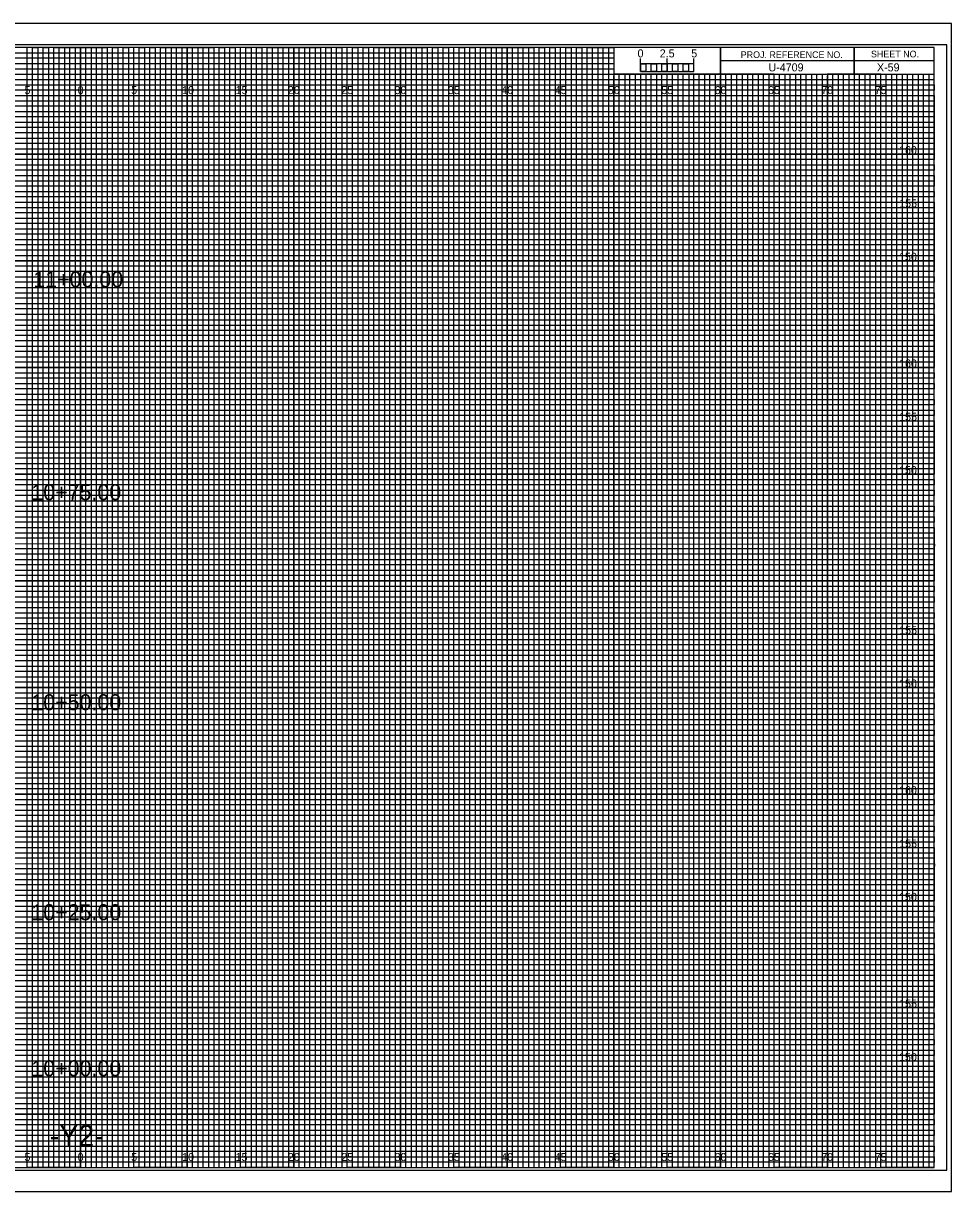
# Model space of a CAD drawing. Extents: x -7 to 162, y -2 to 107.
# Drawn here: x 74.6 to 161.7, y -2.3 to 107.3 of the extents above; entities that cross this region are included whole.
import ezdxf

# ---------------------------------------------------------------- set-up
doc = ezdxf.new("R2010")
doc.units = 0
for name, color, linetype in [('Exist CMT Pavement', 7, 'Continuous'), ('Prop CMT Pvmt Course 1 Wedge', 7, 'Continuous'), ('Prop CMT Pvmt Course 2 Wedge', 7, 'Continuous'), ('Prop CMT Pvmt Course 3 Wedge', 7, 'Continuous'), ('Prop CMT Pvmt Wedge Surface 1', 7, 'Continuous'), ('Prop CMT Pvmt Wedge Surface 2', 7, 'Continuous'), ('Prop CMT Pvmt Wedge Surface 3', 7, 'Continuous'), ('Prop CMT Shear Line', 7, 'Continuous'), ('Prop XS Alignment Label', 7, 'Continuous'), ('Prop XS Bar Scale Labels', 7, 'Continuous'), ('Prop XS Elevation Labels', 7, 'Continuous'), ('Prop XS Label Text', 7, 'Continuous'), ('Prop XS Project Number', 7, 'Continuous'), ('Prop XS Sheet Number', 7, 'Continuous'), ('Prop XS Station Labels', 7, 'Continuous'), ('Scratch_Level_1', 7, 'Continuous'), ('Sheet Cutting Line CELL', 7, 'Continuous')]:
    doc.layers.add(name, color=color, linetype=linetype)

msp = doc.modelspace()

# ---------------------------------------------------------------- linework, layer by layer
at = {"layer": 'Exist CMT Pavement'}
for p, q in [((0, 104.5), (130, 104.5)), ((130, 104.5), (130, 103.99)), ((130, 103.99), (0, 103.99)), ((0, 103.5), (130, 103.5)), ((130, 102.95), (0, 102.95)), ((130, 103.5), (130, 102.95)), ((0, 102), (160, 102))]:
    msp.add_line(p, q, dxfattribs=at)
for points in [[(0, 101.5), (135, 101.5), (160, 101.5), (160, 101), (0, 101)], [(0, 100.5), (160, 100.5), (160, 99.5), (0, 99.5)], [(0, 99), (160, 99), (160, 98.5), (0, 98.49)], [(0, 98), (160, 98), (160, 97), (0, 97)], [(0, 96.5), (160, 96.5), (160, 96), (0, 96)], [(0, 95.5), (160, 95.5), (160, 94.5), (0, 94.5)], [(0, 94), (160, 94), (160, 93.5), (0, 93.5)], [(0, 93), (160, 93), (160, 92), (0, 92)], [(0, 91.5), (160, 91.5), (160, 91), (0, 91)], [(0, 90.5), (160, 90.5), (160, 89.5), (0, 89.5)], [(0, 89), (160, 89), (160, 88.5), (0, 88.5)], [(0, 88), (160, 88), (160, 86.98), (160, 86.5), (160, 86), (0, 86)], [(0, 87), (160, 87), (160, 86.5), (0, 86.5)], [(0, 85.5), (160, 85.5), (160, 84.5), (0, 84.52)], [(0, 84.52), (160, 84.5), (160, 84), (0, 84)], [(0, 83.5), (160, 83.5), (160, 83), (0, 83)], [(0, 82), (160, 82), (160, 81.5), (0, 81.5)], [(0, 81), (160, 81), (160, 80.5), (0, 80.5)], [(-0.04, 79.45), (160, 79.45), (160, 78.94), (-0.04, 78.94)], [(0, 78.5), (160, 78.5), (160, 78), (0, 78)], [(0, 77), (160, 77), (160, 76.5), (0, 76.5)], [(0, 76), (160, 76), (160, 75.5), (0, 75.5)], [(0, 74.5), (160, 74.5), (160, 74), (0, 74)], [(0, 73.5), (160, 73.5), (160, 73), (0, 73)], [(0, 72), (160, 72), (160, 71.5), (0, 71.5)], [(0, 71), (160, 71), (160, 70.5), (0, 70.5)], [(0, 69.5), (160, 69.5), (160, 68.99), (0, 69)], [(0, 68.5), (160, 68.5), (160, 68), (0, 68)], [(0, 67), (160, 67), (160, 66.5), (0, 66.5)], [(0, 66), (160, 66), (160, 65.5), (0, 65.5)], [(0, 64.5), (160, 64.5), (160, 64), (0, 64)], [(0, 63.5), (160, 63.5), (160, 63), (0, 63)], [(0, 62), (160, 62), (160, 61.5), (0, 61.5)], [(0, 61), (160, 61), (160, 60.5), (0, 60.5)], [(0, 59.5), (160, 59.5), (160, 59), (0, 59)], [(0, 58.5), (160.03, 58.45), (160, 58), (0, 58)], [(0, 57), (160, 57), (160, 56.5), (0, 56.5)], [(0, 56), (160, 56), (160, 55.5), (0, 55.5)], [(0, 54.5), (160, 54.5), (160, 54), (0, 54)], [(0, 53.5), (160, 53.5), (160, 53), (0, 53)], [(0, 52), (160, 52), (160, 51.5), (0, 51.5)], [(0, 51), (160, 51), (160, 50.5), (0, 50.5)], [(0, 49.5), (160, 49.5), (160, 49), (0, 49)], [(0, 48.5), (160, 48.5), (160, 48), (0, 48)], [(0, 47), (160, 47), (160, 46.5), (0, 46.5)], [(0, 46), (160, 46), (160, 45.5), (0, 45.5)], [(0, 44.5), (160, 44.5), (160, 44), (0, 44)], [(0, 43.5), (160, 43.5), (160, 43), (0, 43)], [(0, 42), (160, 42), (160, 41.5), (0, 41.5)], [(0, 41), (160, 41), (160, 40.5), (0, 40.5)], [(0, 39.5), (160, 39.5), (160, 38.99), (0, 39)], [(0, 38.5), (160, 38.5), (160, 38), (0, 38)], [(0, 37), (160, 37), (160, 36.5), (0, 36.5)], [(0, 36), (160, 36), (160, 35.5), (0, 35.5)], [(0, 34.5), (160, 34.5), (160, 34), (0, 34)], [(0, 33.5), (160, 33.5), (160, 33), (0, 33)], [(0, 32), (160, 32), (160, 31.5), (0, 31.5)], [(0, 31), (160, 31), (160, 30.5), (0, 30.5)], [(0, 29.5), (160, 29.5), (160, 29), (0, 29)], [(0, 28.5), (160.03, 28.46), (160, 28), (0, 28)], [(0, 27), (160, 27), (160, 26.5), (0, 26.5)], [(0, 26), (160, 26), (160, 25.5), (0, 25.5)], [(0, 24.5), (160, 24.5), (160, 24), (0, 24)], [(0, 23.5), (160, 23.5), (160, 23), (0, 23)], [(0, 22), (160, 22), (160, 21.5), (0, 21.5)], [(0, 21), (160, 21), (160, 20.5), (0, 20.5)], [(0, 19.5), (160, 19.5), (160, 19), (0, 19)], [(0, 18.5), (160, 18.5), (160, 18), (0, 18)], [(0, 17), (160, 17), (160, 16.5), (0, 16.5)], [(0, 16), (160, 16), (160, 15.5), (0, 15.5)], [(0, 14.5), (160, 14.5), (160, 14), (0, 14)], [(0, 13.5), (160, 13.5), (160, 13), (0, 13)], [(0, 12), (160, 12), (160, 11.5), (0, 11.5)], [(0, 11), (160, 11), (160, 10.5), (0, 10.5)], [(0, 9.5), (160, 9.5), (160, 9), (0, 9)], [(0, 8.5), (160, 8.5), (160, 8), (0, 8)], [(0, 7), (160, 7), (160, 6.5), (0, 6.5)], [(0, 6), (160, 6), (160, 5.5), (0, 5.5)], [(0, 4.5), (160, 4.5), (160, 4), (0, 4)], [(0, 3.5), (160, 3.5), (160, 3), (0, 3)], [(0, 2), (160, 2), (160, 1.5), (0, 1.5)], [(0, 1), (160, 1), (160, 0.5), (0, 0.5)]]:
    msp.add_lwpolyline(points, dxfattribs=at)
at = {"layer": 'Prop CMT Pvmt Course 2 Wedge'}
for p, q in [((75, 105), (70, 105)), ((75, 0), (75, 105)), ((85, 105), (80, 105)), ((80, 105), (80, 0)), ((85, 0), (85, 105)), ((95, 105), (90, 105)), ((90, 105), (90, 0)), ((95, 0), (95, 105)), ((105, 105), (100, 105)), ((100, 105), (100, 0)), ((105, 0), (105, 105)), ((115, 105), (110, 105)), ((110, 105), (110, 0)), ((115, 0), (115, 105)), ((125, 105), (120, 105)), ((120, 105), (120, 0)), ((125, 0), (125, 105)), ((130, 105), (130, 0)), ((135, 0), (135, 102.5)), ((145, 102.5), (140, 102.5)), ((140, 102.5), (140, 0)), ((145, 0), (145, 102.5)), ((155, 102.5), (150, 102.5)), ((150, 102.5), (150, 0)), ((155, 0), (155, 102.5)), ((80, 0), (75, 0)), ((90, 0), (85, 0)), ((100, 0), (95, 0)), ((110, 0), (105, 0)), ((120, 0), (115, 0)), ((130, 0), (125, 0)), ((140, 0), (135, 0)), ((150, 0), (145, 0)), ((160, 0), (155, 0)), ((160, 0), (160, 0))]:
    msp.add_line(p, q, dxfattribs=at)
for points in [[(0, 100), (160, 100), (160, 95), (0, 95)], [(0, 90), (160, 90), (160, 85), (0, 85)], [(0, 80), (160, 80), (160, 75), (0, 75)], [(0, 70), (160, 70), (160, 65), (0, 65)], [(0, 60), (160, 60), (160, 55), (0, 55)], [(0, 50), (160, 50), (160, 45), (0, 45)], [(0, 40), (160, 40), (160, 35), (0, 35)], [(0, 30), (160, 30), (160, 25), (0, 25)], [(0, 20), (160, 20), (160, 15), (0, 15)], [(0, 10), (160, 10), (160, 5), (0, 5)]]:
    msp.add_lwpolyline(points, dxfattribs=at)
at = {"layer": 'Prop CMT Pvmt Course 3 Wedge'}
for points in [[(72.5, 0), (77.5, 0), (77.5, 105), (82.5, 105), (82.5, 0), (87.5, 0), (87.5, 105), (92.5, 105), (92.5, 0), (97.5, 0), (97.5, 105), (102.5, 105), (102.5, 0), (107.5, 0), (107.5, 105), (112.5, 105), (112.5, 0), (117.5, 0), (117.5, 105), (122.5, 105), (122.5, 0), (127.5, 0), (127.5, 105), (129.97, 105), (130, 105), (130, 102.5), (132.5, 102.5), (132.5, 0), (137.5, 0), (137.5, 102.5), (142.5, 102.5), (142.5, 0), (147.5, 0), (147.5, 102.5), (152.5, 102.5), (152.5, 0), (157.5, 0), (157.5, 102.5)], [(0, 102.5), (137.5, 102.5)], [(0, 92.5), (160, 92.5), (160, 97.5), (0, 97.5)], [(0, 82.5), (160, 82.5), (160, 87.5), (0, 87.5)], [(0, 72.5), (160, 72.5), (160, 77.5), (0, 77.5)], [(0, 62.5), (160, 62.5), (160, 67.5), (0, 67.5)], [(0, 52.5), (160, 52.5), (160, 57.5), (0, 57.5)], [(0, 42.5), (160, 42.5), (160, 47.5), (0, 47.5)], [(0, 32.5), (160, 32.5), (160, 37.5), (0, 37.5)], [(0, 22.5), (160, 22.5), (160, 27.5), (0, 27.5)], [(0, 12.5), (160, 12.5), (160, 17.5), (0, 17.5)], [(0, 2.5), (160, 2.5), (160, 7.5), (0, 7.5)]]:
    msp.add_lwpolyline(points, dxfattribs=at)
at = {"layer": 'Prop CMT Pvmt Wedge Surface 1'}
for p, q in [((152.5, 105), (152.5, 102.5)), ((152.5, 102.5), (152.5, 105)), ((160, 103.75), (140, 103.75)), ((140, 103.75), (140, 102.5)), ((140, 102.5), (160, 102.5))]:
    msp.add_line(p, q, dxfattribs=at)
for points in [[(160, 105), (0, 105), (0, 0), (160, 0)], [(140, 105), (130, 105), (130, 102.52), (140, 102.52)], [(160, 105), (140, 105), (140, 102.5), (160, 102.5)]]:
    msp.add_lwpolyline(points, close=True, dxfattribs=at)
at = {"layer": 'Prop CMT Pvmt Wedge Surface 2'}
for p, q in [((133.5, 102.5), (133, 102.5)), ((133, 102.5), (133, 0)), ((133.5, 0), (133.5, 102.5)), ((134.5, 102.5), (134, 102.5)), ((134, 102.5), (134, 0)), ((134.5, 0), (134.5, 102.5)), ((133, 0), (132.5, 0)), ((134, 0), (133.5, 0))]:
    msp.add_line(p, q, dxfattribs=at)
for points in [[(75, 0), (75.5, 0), (75.5, 105), (76, 105), (76, 0)], [(76, 0), (76.5, 0), (76.5, 105), (77, 105), (77, 0)], [(77.5, 0), (78, 0), (78, 105), (78.5, 105), (78.5, 0)], [(78.5, 0), (79, 0), (79, 105), (79.5, 105), (79.5, 0)], [(80, 0), (80.5, 0), (80.5, 105), (81, 105), (81, 0)], [(81, 0), (81.5, 0), (81.5, 105), (82, 105), (82, 0)], [(82.5, 0), (83, 0), (83, 105), (83.5, 105), (83.5, 0)], [(83.5, 0), (84, 0), (84, 105), (84.5, 105), (84.5, 0)], [(85, 0), (85.5, 0), (85.5, 105), (86, 105), (86, 0)], [(86, 0), (86.5, 0), (86.5, 105), (87, 105), (87, 0)], [(87.5, 0), (88, 0), (88, 105), (88.5, 105), (88.5, 0)], [(88.5, 0), (89, 0), (89, 105), (89.5, 105), (89.5, 0)], [(90, 0), (90.5, 0), (90.5, 105), (91, 105), (91, 0)], [(91, 0), (91.5, 0), (91.5, 105), (92, 105), (92, 0)], [(92.5, 0), (93, 0), (93, 105), (93.5, 105), (93.5, 0)], [(93.5, 0), (94, 0), (94, 105), (94.5, 105), (94.5, 0)], [(95, 0), (95.5, 0), (95.5, 105), (96, 105), (96, 0)], [(96, 0), (96.5, 0), (96.5, 105), (97, 105), (97, 0)], [(97.5, 0), (98, 0), (98, 105), (98.5, 105), (98.5, 0)], [(98.5, 0), (99, 0), (99, 105), (99.5, 105), (99.5, 0)], [(100, 0), (100.5, 0), (100.5, 105), (101, 105), (101, 0)], [(101, 0), (101.5, 0), (101.5, 105), (102, 105), (102, 0)], [(102.5, 0), (103, 0), (103, 105), (103.5, 105), (103.5, 0)], [(103.5, 0), (104, 0), (104, 105), (104.5, 105), (104.5, 0)], [(105, 0), (105.5, 0), (105.5, 105), (106, 105), (106, 0)], [(106, 0), (106.5, 0), (106.5, 105), (107, 105), (107, 0)], [(107.5, 0), (108, 0), (108, 105), (108.5, 105), (108.5, 0)], [(108.5, 0), (109, 0), (109, 105), (109.5, 105), (109.5, 0)], [(110, 0), (110.5, 0), (110.5, 105), (111, 105), (111, 0)], [(111, 0), (111.5, 0), (111.5, 105), (112, 105), (112, 0)], [(112.5, 0), (113, 0), (113, 105), (113.5, 105), (113.5, 0)], [(113.5, 0), (114, 0), (114, 105), (114.5, 105), (114.5, 0)], [(115, 0), (115.5, 0), (115.5, 105), (116, 105), (116, 0)], [(116, 0), (116.5, 0), (116.5, 105), (117, 105), (117, 0)], [(117.5, 0), (118, 0), (118, 105), (118.5, 105), (118.5, 0)], [(118.5, 0), (119, 0), (119, 105), (119.5, 105), (119.5, 0)], [(120, 0), (120.5, 0), (120.5, 105), (121, 105), (121, 0)], [(121, 0), (121.5, 0), (121.5, 105), (122, 105), (122, 0)], [(122.5, 0), (123, 0), (123, 105), (123.5, 105), (123.5, 0)], [(123.5, 0), (124, 0), (124, 105), (124.5, 105), (124.5, 0)], [(125, 0), (125.5, 0), (125.5, 105), (126, 105), (126, 0)], [(126, 0), (126.5, 0), (126.5, 105), (127, 105), (127, 0)], [(127.5, 0), (128, 0), (128, 105), (128.5, 105), (128.5, 0)], [(128.5, 0), (129, 0), (129, 105), (129.5, 105), (129.5, 0)], [(130, 0), (130.5, 0), (130.5, 102.5), (131.01, 102.5), (131.01, 0)], [(131, 0), (131.5, 0), (131.5, 102.5), (132, 102.5), (132, 0)], [(135, 0), (135.49, 0), (135.49, 102.5), (136, 102.5), (136, 0)], [(136, 0), (136.5, 0), (136.5, 102.5), (137.03, 102.5), (137.03, 0)], [(137.5, 0), (138, 0), (138, 102.5), (138.5, 102.5), (138.5, 0)], [(138.5, 0), (139, 0), (139, 102.5), (139.5, 102.5), (139.5, 0)], [(140, 0), (140.5, 0), (140.5, 102.5), (141, 102.5), (141, 0)], [(141, 0), (141.5, 0), (141.5, 102.5), (142, 102.5), (142, 0)], [(142.5, 0), (143, 0), (143, 102.5), (143.5, 102.5), (143.5, 0)], [(143.5, 0), (144, 0), (144, 102.5), (144.5, 102.5), (144.5, 0)], [(145, 0), (145.5, 0), (145.5, 102.5), (146, 102.5), (146, 0)], [(146, 0), (146.5, 0), (146.5, 102.5), (147, 102.5), (147, 0)], [(147.5, 0), (148, 0), (148, 102.5), (148.5, 102.5), (148.5, 0)], [(148.5, 0), (149, 0), (149, 102.5), (149.5, 102.5), (149.5, 0)], [(150, 0), (150.5, 0), (150.5, 102.5), (151, 102.5), (151, 0)], [(151, 0), (151.5, 0), (151.5, 102.5), (152, 102.5), (152, 0)], [(152.5, 0), (153, 0), (153, 102.5), (153.5, 102.5), (153.5, 0)], [(153.5, 0), (154, 0), (154, 102.5), (154.5, 102.5), (154.5, 0)], [(155, 0), (155.5, 0), (155.5, 102.5), (156, 102.5), (156, 0)], [(156, 0), (156.5, 0), (156.5, 102.5), (157, 102.5), (157, 0)], [(157.5, 0), (158, 0), (158, 102.5), (158.5, 102.5), (158.5, 0)], [(158.5, 0), (159, 0), (159, 102.5), (159.5, 102.5), (159.5, 0)]]:
    msp.add_lwpolyline(points, dxfattribs=at)
at = {"layer": 'Prop CMT Pvmt Wedge Surface 3'}
for p, q in [((132.5, 102.75), (132.5, 103.95)), ((132.5, 103.45), (132.5, 103.95)), ((135, 102.75), (135, 103.95)), ((137.5, 102.75), (137.5, 103.95)), ((137.5, 103.45), (137.5, 103.95))]:
    msp.add_line(p, q, dxfattribs=at)
for points in [[(137.5, 103.45), (132.5, 103.45), (132.5, 102.75), (137.5, 102.75)], [(132.5, 103.45), (133, 103.45), (133, 102.75), (132.5, 102.75)], [(133.5, 103.45), (134, 103.45), (134, 102.75), (133.5, 102.75)], [(134.5, 103.45), (135, 103.45), (135, 102.75), (134.5, 102.75)], [(135.5, 103.45), (136, 103.45), (136, 102.75), (135.5, 102.75)], [(136.5, 103.45), (137, 103.45), (137, 102.75), (136.5, 102.75)]]:
    msp.add_lwpolyline(points, close=True, dxfattribs=at)
at = {"layer": 'Prop CMT Shear Line'}
msp.add_lwpolyline([(-5.4, -0.25), (161.2, -0.25), (161.2, 105.25), (-5.4, 105.25)], close=True, dxfattribs=at)
at = {"layer": 'Prop XS Label Text'}
msp.add_lwpolyline([(-6.7, -2.25), (161.65, -2.25), (161.65, 107.25), (-6.7, 107.25)], close=True, dxfattribs=at)
at = {"layer": 'Scratch_Level_1'}
for p, q in [((75, 0), (75, 105)), ((80, 0), (80, 105)), ((85, 0), (85, 105)), ((90, 0), (90, 105)), ((95, 0), (95, 105)), ((100, 0), (100, 105)), ((105, 0), (105, 105)), ((110, 0), (110, 105)), ((115, 0), (115, 105)), ((120, 0), (120, 105)), ((125, 0), (125, 105)), ((130, 0), (130, 102.34)), ((135, 0), (135, 102.34)), ((140, 0), (140, 102.34)), ((145, 0), (145, 102.34)), ((150, 0), (150, 102.34)), ((155, 0), (155, 102.34)), ((0, 100), (160, 100)), ((0, 95), (160, 95)), ((0, 90), (160, 90)), ((0, 85), (160, 85)), ((0, 80), (160, 80)), ((0, 75), (160, 75)), ((0, 70), (160, 70)), ((0, 65), (160, 65)), ((0, 60), (160, 60)), ((0, 55), (160, 55)), ((0, 50), (160, 50)), ((0, 45), (160, 45)), ((0, 40), (160, 40)), ((0, 35), (160, 35)), ((0, 30), (160, 30)), ((0, 25), (160, 25)), ((0, 20), (160, 20)), ((0, 15), (160, 15)), ((0, 10), (160, 10)), ((0, 5), (160, 5))]:
    msp.add_line(p, q, dxfattribs=at)
at = {"layer": 'Sheet Cutting Line CELL'}
for p, q in [((161.65, 107.25), (-6.7, 107.25)), ((-6.7, -2.25), (161.65, -2.25))]:
    msp.add_line(p, q, dxfattribs=at)

# ---------------------------------------------------------------- texts
at = {"layer": 'Prop CMT Pvmt Course 1 Wedge'}
for s, p in [('5', (74.74, 100.62)), ('0', (79.73, 100.62)), ('0', (79.73, 100.62)), ('5', (84.74, 100.62)), ('10', (89.52, 100.62)), ('15', (94.53, 100.62)), ('20', (99.43, 100.62)), ('25', (104.44, 100.62)), ('30', (109.43, 100.62)), ('35', (114.44, 100.62)), ('40', (119.43, 100.62)), ('45', (124.44, 100.62)), ('50', (129.43, 100.62)), ('55', (134.44, 100.62)), ('60', (139.43, 100.62)), ('65', (144.44, 100.62)), ('70', (149.43, 100.62)), ('75', (154.44, 100.62)), ('5', (74.74, 0.62)), ('0', (79.73, 0.62)), ('0', (79.73, 0.62)), ('5', (84.74, 0.62)), ('10', (89.52, 0.62)), ('15', (94.53, 0.62)), ('20', (99.43, 0.62)), ('25', (104.44, 0.62)), ('30', (109.43, 0.62)), ('35', (114.44, 0.62)), ('40', (119.43, 0.62)), ('45', (124.44, 0.62)), ('50', (129.43, 0.62)), ('55', (134.44, 0.62)), ('60', (139.43, 0.62)), ('65', (144.44, 0.62)), ('70', (149.43, 0.62)), ('75', (154.44, 0.62))]:
    msp.add_text(s, height=0.75, dxfattribs=at).set_placement(p)
at = {"layer": 'Prop CMT Pvmt Wedge Surface 1'}
for s, p in [('PROJ. REFERENCE NO.', (141.88, 104)), ('SHEET NO.', (154.09, 104.06))]:
    msp.add_text(s, height=0.625, dxfattribs=at).set_placement(p)
at = {"layer": 'Prop CMT Pvmt Wedge Surface 3'}
msp.add_text('0', height=0.75, dxfattribs=at).set_placement((132.21, 104.06))
at = {"layer": 'Prop XS Alignment Label'}
msp.add_text('-Y2-', height=2, dxfattribs=at).set_placement((77.12, 2))
at = {"layer": 'Prop XS Bar Scale Labels'}
for s, p in [('2.5', (134.29, 104.06)), ('5', (137.24, 104.06))]:
    msp.add_text(s, height=0.75, dxfattribs=at).set_placement(p)
at = {"layer": 'Prop XS Elevation Labels'}
for s, p in [('160', (156.72, 95)), ('155', (156.73, 90)), ('150', (156.72, 85)), ('160', (156.72, 75)), ('155', (156.73, 70)), ('150', (156.72, 65)), ('155', (156.73, 50)), ('150', (156.72, 45)), ('160', (156.72, 35)), ('155', (156.73, 30)), ('150', (156.72, 25)), ('155', (156.73, 15)), ('150', (156.72, 10))]:
    msp.add_text(s, height=0.75, dxfattribs=at).set_placement(p)
at = {"layer": 'Prop XS Project Number'}
msp.add_text('U-4709', height=0.75, dxfattribs=at).set_placement((144.48, 102.75))
at = {"layer": 'Prop XS Sheet Number'}
msp.add_text('X-59', height=0.75, dxfattribs=at).set_placement((154.65, 102.75))
at = {"layer": 'Prop XS Station Labels'}
for s, p in [('11+00.00', (75.57, 82.51)), ('10+75.00', (75.39, 62.56)), ('10+50.00', (75.39, 42.87)), ('10+25.00', (75.39, 23.19)), ('10+00.00', (75.39, 8.56))]:
    msp.add_text(s, height=1.5, dxfattribs=at).set_placement(p)

doc.saveas('drawing.dxf')
